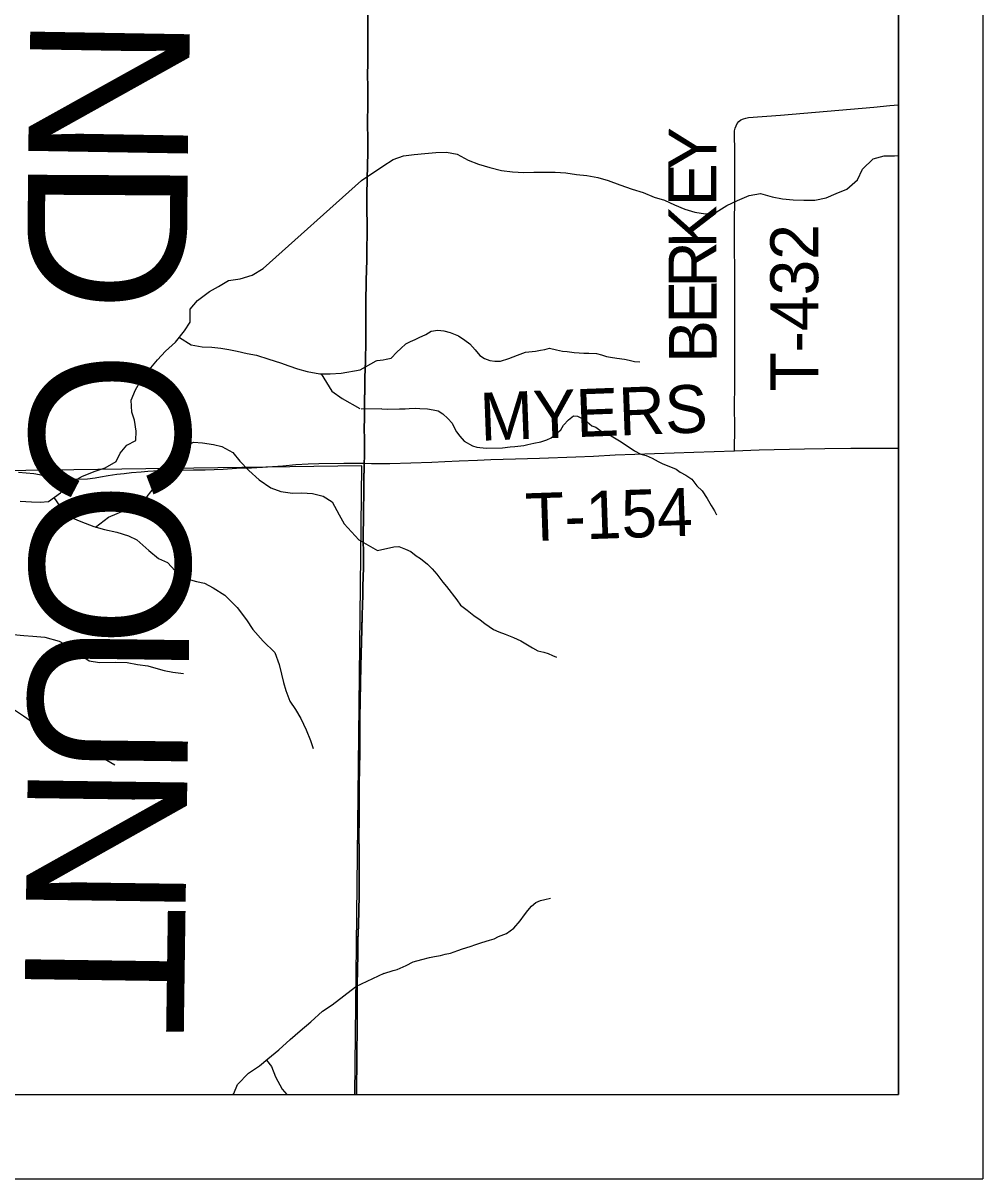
# Model space of a CAD drawing. Extents: x 0 to 34, y 0 to 22.
# Drawn here: x 7.861 to 9, y 14 to 15.371 of the extents above; entities that cross this region are included whole.
import ezdxf

# ---------------------------------------------------------------- set-up
doc = ezdxf.new("R2010")
doc.units = 0
for name, color, linetype in [('Default', 7, 'Continuous'), ('GM_X_County_Text', 7, 'Continuous'), ('GM_X_Interstate_Route', 7, 'Continuous'), ('GM_X_Minor_River', 7, 'Continuous'), ('GM_X_Township_Road', 7, 'Continuous'), ('GM_X_Township_Road_Text', 7, 'Continuous'), ('SH_Cut_Line', 7, 'Continuous'), ('SH_Data', 7, 'Continuous')]:
    doc.layers.add(name, color=color, linetype=linetype)

msp = doc.modelspace()

# ---------------------------------------------------------------- linework, layer by layer
at = {"layer": 'Default'}
msp.add_lwpolyline([(7.1737, 14.1), (8.2548, 14.1), (8.263, 14.8458), (7.1806, 14.8307)], close=True, dxfattribs=at)
at = {"layer": 'GM_X_Interstate_Route'}
for points in [[(8.2703, 15.3819), (8.2702, 15.3628), (8.2701, 15.3535), (8.2702, 15.3459), (8.2703, 15.3357), (8.2701, 15.3227), (8.27, 15.3103), (8.2701, 15.2947), (8.2702, 15.2762), (8.27, 15.2515), (8.2703, 15.2332), (8.2703, 15.2173), (8.2694, 15.1864), (8.2691, 15.1669), (8.2692, 15.1484), (8.2694, 15.1335), (8.2694, 15.1187), (8.2692, 15.106), (8.2691, 15.0903), (8.2683, 15.0658), (8.2681, 15.0391), (8.268, 15.0245), (8.2678, 15.0102), (8.268, 14.9935), (8.2674, 14.9699), (8.2669, 14.9504), (8.2669, 14.9375), (8.2665, 14.9229), (8.2663, 14.9134), (8.2662, 14.904), (8.2661, 14.8885), (8.2662, 14.8792), (8.2662, 14.8689), (8.2663, 14.8563), (8.2661, 14.8495), (8.266, 14.8449), (8.2656, 14.8297), (8.2654, 14.8172), (8.2651, 14.7896), (8.2649, 14.7585), (8.2651, 14.742), (8.2651, 14.7239), (8.2649, 14.715), (8.2645, 14.7023), (8.2642, 14.6921), (8.2638, 14.681), (8.2637, 14.6681), (8.2629, 14.637), (8.2621, 14.609), (8.2609, 14.5469), (8.2607, 14.5068), (8.2606, 14.4854), (8.2602, 14.4707), (8.2602, 14.4471), (8.26, 14.4256), (8.2595, 14.407), (8.26, 14.3884), (8.26, 14.3612), (8.2602, 14.3362), (8.2593, 14.3015), (8.2586, 14.2834), (8.2586, 14.2645), (8.258, 14.25), (8.2577, 14.228), (8.2575, 14.2115), (8.2575, 14.1836), (8.2572, 14.1432), (8.2568, 14.1028), (8.2568, 14.1), (8.9, 14.1), (8.9, 16.8746)], [(3.2011, 14.1), (8.2568, 14.1), (8.2568, 14.1028), (8.2572, 14.1432), (8.2575, 14.1836), (8.2575, 14.2115), (8.2577, 14.228), (8.258, 14.25), (8.2586, 14.2645), (8.2586, 14.2834), (8.2593, 14.3015), (8.2602, 14.3362), (8.26, 14.3612), (8.26, 14.3884), (8.2595, 14.407), (8.26, 14.4256), (8.2602, 14.4471), (8.2602, 14.4707), (8.2606, 14.4854), (8.2607, 14.5068), (8.2609, 14.5469), (8.2621, 14.609), (8.2629, 14.637), (8.2637, 14.6681), (8.2638, 14.681), (8.2642, 14.6921), (8.2645, 14.7023), (8.2649, 14.715), (8.2651, 14.7239), (8.2651, 14.742), (8.2649, 14.7585), (8.2651, 14.7896), (8.2654, 14.8172), (8.2656, 14.8297), (8.266, 14.8449), (8.2661, 14.8495), (8.2663, 14.8563), (8.2662, 14.8689), (8.2662, 14.8792), (8.2661, 14.8885), (8.2662, 14.904), (8.2663, 14.9134), (8.2665, 14.9229), (8.2669, 14.9375), (8.2669, 14.9504), (8.2674, 14.9699), (8.268, 14.9935), (8.2678, 15.0102), (8.268, 15.0245), (8.2681, 15.0391), (8.2683, 15.0658), (8.2691, 15.0903), (8.2692, 15.106), (8.2694, 15.1187), (8.2694, 15.1335), (8.2692, 15.1484), (8.2691, 15.1669), (8.2694, 15.1864), (8.2703, 15.2173), (8.2703, 15.2332), (8.27, 15.2515), (8.2702, 15.2762), (8.2701, 15.2947), (8.27, 15.3103), (8.2701, 15.3227), (8.2703, 15.3357), (8.2702, 15.3459), (8.2701, 15.3535), (8.2702, 15.3628), (8.2703, 15.3819)]]:
    msp.add_lwpolyline(points, dxfattribs=at)
at = {"layer": 'GM_X_Minor_River'}
for points in [[(8.2626, 15.1841), (8.288, 15.2014), (8.3003, 15.2092), (8.3125, 15.2136), (8.3251, 15.2153), (8.338, 15.2163), (8.351, 15.2176), (8.3635, 15.2178), (8.3761, 15.2154), (8.3893, 15.2084), (8.4014, 15.2037), (8.415, 15.1997), (8.429, 15.1961), (8.4419, 15.1944), (8.4552, 15.1938), (8.4674, 15.194), (8.4803, 15.1942), (8.4925, 15.1941), (8.5054, 15.1935), (8.518, 15.1914), (8.5301, 15.1901), (8.543, 15.1877), (8.5555, 15.1841), (8.5691, 15.179), (8.5839, 15.1738), (8.5968, 15.1699), (8.61, 15.1644), (8.6221, 15.1608), (8.6342, 15.1553), (8.6463, 15.1502), (8.6584, 15.1466), (8.671, 15.1449), (8.6835, 15.1466), (8.6962, 15.1548), (8.7088, 15.1607), (8.7226, 15.1663), (8.736, 15.1688), (8.75, 15.1648), (8.7621, 15.1627), (8.775, 15.1614), (8.7876, 15.1608), (8.8005, 15.161), (8.8139, 15.1639), (8.8261, 15.1687), (8.8387, 15.1738), (8.8514, 15.1851), (8.8573, 15.1976), (8.8697, 15.2099), (8.8827, 15.2136), (8.8952, 15.2134), (8.9, 15.2139)], [(8.2626, 15.1841), (8.1463, 15.0797)], [(7.8577, 14.8038), (7.8713, 14.803), (7.8816, 14.8027), (7.8914, 14.8035), (7.9058, 14.8138), (7.9198, 14.8267), (7.9319, 14.8336), (7.9467, 14.8393), (7.9588, 14.8435), (7.9717, 14.8508), (7.9766, 14.8607), (7.9842, 14.8702), (7.9951, 14.8759), (7.9955, 14.8869), (7.9936, 14.8998), (7.9905, 14.9096), (7.9897, 14.9237), (7.9946, 14.9358), (8.0006, 14.9461), (8.0089, 14.9575), (8.0207, 14.9716), (8.0301, 14.9819), (8.0422, 14.9925), (8.0528, 15.0058), (8.0596, 15.0161), (8.0596, 15.0317), (8.0683, 15.0419), (8.0826, 15.0526), (8.0932, 15.0587), (8.105, 15.0656), (8.119, 15.0675), (8.133, 15.0721), (8.1463, 15.0797)], [(8.2812, 14.9707), (8.2886, 14.9714), (8.2922, 14.9723), (8.2979, 14.9736), (8.3047, 14.9805), (8.3096, 14.9851), (8.3153, 14.9904), (8.321, 14.9931), (8.3263, 14.9958), (8.3312, 14.9981), (8.3392, 15.0016), (8.3456, 15.0054), (8.3532, 15.0066), (8.3604, 15.0059), (8.368, 15.004), (8.3779, 14.9999), (8.3855, 14.995), (8.3912, 14.9904), (8.3977, 14.9836), (8.4031, 14.9768), (8.4088, 14.973), (8.4149, 14.9708), (8.4209, 14.97), (8.4278, 14.9701), (8.4376, 14.9731), (8.4429, 14.9751), (8.4478, 14.977), (8.4573, 14.9805), (8.4694, 14.982), (8.4751, 14.9832), (8.4804, 14.984), (8.4857, 14.9852), (8.4941, 14.9833), (8.5013, 14.9818), (8.5066, 14.9814), (8.515, 14.9803), (8.5211, 14.98), (8.5264, 14.9796), (8.5325, 14.9793), (8.5416, 14.9789), (8.5477, 14.9774), (8.5534, 14.9756), (8.5583, 14.9748), (8.5659, 14.9737), (8.575, 14.9723), (8.5803, 14.9711), (8.5868, 14.9696), (8.5929, 14.9693)], [(8.0467, 14.9982), (8.0608, 14.9895), (8.0737, 14.9869), (8.0851, 14.9866), (8.0957, 14.9855), (8.1052, 14.984), (8.1151, 14.9817), (8.1272, 14.9791), (8.1382, 14.9769), (8.1527, 14.9724), (8.1667, 14.9679), (8.1766, 14.9645), (8.1868, 14.9607), (8.1982, 14.9577), (8.2134, 14.9551), (8.2256, 14.9548), (8.2388, 14.9556), (8.2611, 14.9596)], [(8.2611, 14.9596), (8.2802, 14.9705), (8.2812, 14.9707)], [(8.215, 14.9551), (8.2274, 14.9345), (8.24, 14.9258), (8.2608, 14.9138)], [(8.2869, 14.9135), (8.2623, 14.9131)], [(8.2869, 14.9135), (8.2933, 14.9132), (8.3077, 14.9136), (8.3146, 14.9136), (8.3195, 14.914), (8.3267, 14.9141), (8.332, 14.9137), (8.3411, 14.9134), (8.348, 14.9123), (8.3537, 14.9112), (8.3594, 14.9074), (8.3651, 14.9021), (8.3705, 14.8964), (8.3728, 14.8911), (8.3754, 14.8862), (8.3793, 14.8809), (8.3846, 14.8752), (8.3945, 14.8695), (8.3995, 14.868), (8.4105, 14.8669), (8.4302, 14.867), (8.4393, 14.8682), (8.4446, 14.8686), (8.4552, 14.8698), (8.4602, 14.871), (8.4674, 14.8725), (8.4757, 14.8741), (8.4825, 14.8768), (8.4878, 14.8791), (8.4927, 14.8829), (8.4992, 14.8886), (8.5025, 14.894), (8.5082, 14.9005), (8.5143, 14.905), (8.5192, 14.9047), (8.5276, 14.9002), (8.536, 14.8934), (8.5409, 14.8915), (8.547, 14.8869), (8.5519, 14.8854), (8.5588, 14.8813), (8.5687, 14.8753), (8.579, 14.8688), (8.5866, 14.8636), (8.5942, 14.8598), (8.6007, 14.8579), (8.6075, 14.8549), (8.6147, 14.8511), (8.6204, 14.8481), (8.6273, 14.8455), (8.636, 14.8417), (8.641, 14.8383), (8.6475, 14.8349), (8.6547, 14.83), (8.6608, 14.8221), (8.6669, 14.816), (8.673, 14.8069), (8.6776, 14.7986), (8.6815, 14.7925), (8.6838, 14.7876)], [(7.9473, 14.7731), (7.9628, 14.7851), (7.9833, 14.7936), (7.9965, 14.8012), (8.0086, 14.8096), (8.0173, 14.8206), (8.0244, 14.8336), (8.0323, 14.8431), (8.0406, 14.8557), (8.0527, 14.8686), (8.0633, 14.874), (8.0743, 14.8732), (8.0872, 14.871), (8.097, 14.8687), (8.1103, 14.8616), (8.1186, 14.8513), (8.1293, 14.8404), (8.1414, 14.829), (8.1551, 14.8199), (8.1672, 14.8154), (8.1809, 14.8135), (8.1918, 14.8136), (8.2047, 14.8129), (8.2172, 14.8099), (8.2278, 14.803), (8.2362, 14.7875), (8.2423, 14.7769), (8.2596, 14.7581)], [(7.8979, 14.8081), (7.9102, 14.7903), (7.9204, 14.7839), (7.9299, 14.7797), (7.9451, 14.7737), (7.958, 14.7703), (7.9724, 14.7673), (7.9864, 14.7628), (7.9963, 14.7579), (8.0103, 14.7454), (8.0221, 14.7359), (8.0327, 14.731), (8.0418, 14.7212), (8.0543, 14.7121), (8.0672, 14.7087), (8.0767, 14.7065), (8.0869, 14.7012), (8.1006, 14.6925), (8.1154, 14.6777), (8.1264, 14.6633), (8.134, 14.6516), (8.1462, 14.6379), (8.1599, 14.6243), (8.1652, 14.6103), (8.1679, 14.5985), (8.1702, 14.5886), (8.1729, 14.5791), (8.1778, 14.5666), (8.1843, 14.5568), (8.1908, 14.5462), (8.1972, 14.5325), (8.2022, 14.52), (8.2053, 14.5105)], [(8.2596, 14.7581), (8.2819, 14.7453)], [(8.2819, 14.7453), (8.3011, 14.7497), (8.3071, 14.7501), (8.3151, 14.7471), (8.3212, 14.7441), (8.3276, 14.7392), (8.3326, 14.7358), (8.341, 14.729), (8.3467, 14.7237), (8.352, 14.7172), (8.3593, 14.7077), (8.3635, 14.7028), (8.3757, 14.6869), (8.3803, 14.6805), (8.3883, 14.6744), (8.396, 14.6684), (8.4036, 14.6631), (8.4093, 14.6589), (8.4192, 14.6517), (8.4257, 14.6487), (8.4333, 14.6461), (8.4432, 14.6423), (8.4519, 14.6382), (8.4599, 14.6333), (8.4656, 14.6299), (8.4721, 14.6265), (8.4793, 14.6246), (8.4842, 14.6231), (8.4892, 14.6209), (8.4941, 14.619)], [(7.8494, 14.6459), (7.8623, 14.6444), (7.8729, 14.6437), (7.887, 14.6426), (7.904, 14.6377), (7.9143, 14.6324), (7.9268, 14.6234), (7.9398, 14.6143), (7.9519, 14.6124), (7.9713, 14.6129), (7.9849, 14.6125), (7.9971, 14.6103), (8.0092, 14.6084), (8.0187, 14.6058), (8.0286, 14.6032), (8.0388, 14.6009), (8.0517, 14.5995)], [(7.6894, 14.6185), (7.7001, 14.5938), (7.713, 14.584), (7.7267, 14.5806), (7.7388, 14.5807), (7.7513, 14.5841), (7.7612, 14.586), (7.771, 14.5868), (7.7805, 14.5876), (7.793, 14.5854), (7.8056, 14.5805), (7.8155, 14.576), (7.828, 14.5692), (7.8462, 14.5597), (7.8618, 14.5492), (7.8725, 14.5416), (7.8858, 14.5329), (7.8979, 14.5269), (7.9074, 14.5224), (7.9215, 14.5148), (7.931, 14.5107), (7.9405, 14.5073), (7.956, 14.4994), (7.9701, 14.4911)], [(8.2893, 14.2435), (8.3003, 14.247), (8.3052, 14.2485), (8.3158, 14.2532), (8.3241, 14.2574), (8.3343, 14.2601), (8.3434, 14.2624), (8.3495, 14.2636), (8.3567, 14.2651), (8.362, 14.2667), (8.3685, 14.2678), (8.3772, 14.2709), (8.3825, 14.2728), (8.3916, 14.2756), (8.3984, 14.2779), (8.4056, 14.2802), (8.4147, 14.2833), (8.42, 14.2848), (8.4253, 14.2875), (8.4348, 14.291), (8.4435, 14.2975), (8.451, 14.3062), (8.4563, 14.3131), (8.46, 14.3185), (8.4646, 14.3234), (8.4695, 14.328), (8.4752, 14.3303), (8.4801, 14.3315), (8.4869, 14.333)], [(8.2893, 14.2435), (8.2555, 14.2279)], [(8.1105, 14.1), (8.1112, 14.1014), (8.1157, 14.1121), (8.1286, 14.1254), (8.1418, 14.1342), (8.1517, 14.1422), (8.1649, 14.1532), (8.1782, 14.1654), (8.1899, 14.1757), (8.2027, 14.1863), (8.2167, 14.1989), (8.2281, 14.2065), (8.2555, 14.2279)], [(8.1501, 14.1409), (8.1559, 14.1334), (8.1608, 14.1209), (8.1688, 14.1065), (8.1743, 14.1)]]:
    msp.add_lwpolyline(points, dxfattribs=at)
at = {"layer": 'GM_X_Township_Road'}
msp.add_line((8.2663, 14.848), (8.2663, 14.8489), dxfattribs=at)
for points in [[(8.2663, 14.8489), (8.2665, 14.8558), (8.2664, 14.8683), (8.2664, 14.8787), (8.2663, 14.888), (8.2664, 14.9035), (8.2666, 14.9128), (8.2667, 14.9223), (8.2671, 14.937), (8.2671, 14.9499), (8.2676, 14.9694), (8.2682, 14.993), (8.268, 15.0096), (8.2682, 15.0239), (8.2684, 15.0386), (8.2685, 15.0652), (8.2693, 15.0898), (8.2694, 15.1055), (8.2696, 15.1182), (8.2696, 15.1329), (8.2694, 15.1479), (8.2693, 15.1663), (8.2696, 15.1858), (8.2705, 15.2168), (8.2705, 15.2327), (8.2702, 15.2509), (8.2704, 15.2756), (8.2703, 15.2942), (8.2702, 15.3097), (8.2703, 15.3222), (8.2705, 15.3352), (8.2704, 15.3454), (8.2703, 15.353), (8.2704, 15.3623), (8.2706, 15.3813)], [(8.7055, 15.2431), (8.7061, 15.2462), (8.7071, 15.2491), (8.7086, 15.2518), (8.7106, 15.2542), (8.713, 15.2561), (8.7158, 15.2576), (8.7188, 15.2584), (8.7219, 15.2589), (8.7597, 15.2616), (8.8014, 15.2652), (8.8708, 15.2713), (8.8896, 15.2733), (8.9, 15.2742)], [(8.7055, 14.8637), (8.7055, 14.8669), (8.7056, 14.8884), (8.7055, 14.9195), (8.7056, 14.9382), (8.7057, 14.9956), (8.7057, 15.0441), (8.7057, 15.0673), (8.7055, 15.1156), (8.7054, 15.1374), (8.7058, 15.1591), (8.7059, 15.1778), (8.7059, 15.1996), (8.7058, 15.2182), (8.7053, 15.24), (8.7055, 15.2431)], [(8.2663, 14.8489), (8.2747, 14.8487), (8.2778, 14.8486), (8.2965, 14.8487), (8.3213, 14.8493), (8.3462, 14.8502), (8.3617, 14.851), (8.3786, 14.8519), (8.4006, 14.8527), (8.4164, 14.8532), (8.4456, 14.8541), (8.4741, 14.8549), (8.5172, 14.8565), (8.5381, 14.8573), (8.5637, 14.8587), (8.6103, 14.8603), (8.6569, 14.8619), (8.7055, 14.8637)], [(8.7055, 14.8637), (8.7346, 14.8648), (8.7884, 14.8659)], [(8.7884, 14.8659), (8.8123, 14.8664), (8.8434, 14.8669), (8.8839, 14.8668), (8.9, 14.8668)], [(7.8558, 14.8382), (7.8651, 14.8374), (7.8742, 14.8366), (7.8806, 14.8355), (7.8886, 14.8337), (7.8987, 14.8317), (7.906, 14.8307), (7.9142, 14.83), (7.925, 14.8298), (7.9377, 14.8304), (7.9467, 14.8315), (7.9531, 14.8326), (7.9624, 14.8343), (7.9724, 14.8358), (7.9814, 14.8369), (7.9901, 14.8378), (8.0014, 14.8388), (8.0091, 14.8393), (8.0161, 14.8397), (8.0233, 14.8402), (8.0347, 14.8407), (8.0635, 14.8409), (8.0775, 14.8411), (8.0986, 14.842), (8.1144, 14.8429), (8.1322, 14.8436), (8.1454, 14.8442), (8.1571, 14.8452), (8.1696, 14.846), (8.1848, 14.8473), (8.1997, 14.8481), (8.2122, 14.8485), (8.242, 14.849), (8.2596, 14.849), (8.2663, 14.8489)], [(8.257, 14.1), (8.257, 14.1022), (8.2574, 14.1426), (8.2577, 14.1831), (8.2577, 14.211), (8.2579, 14.2274), (8.2582, 14.2494), (8.2588, 14.2639), (8.2588, 14.2829), (8.2595, 14.3009), (8.2604, 14.3356), (8.2602, 14.3607), (8.2602, 14.3879), (8.2597, 14.4065), (8.2602, 14.4251), (8.2604, 14.4465), (8.2604, 14.4701), (8.2608, 14.4848), (8.2609, 14.5063), (8.2611, 14.5463), (8.2623, 14.6085), (8.2631, 14.6365), (8.2639, 14.6675), (8.264, 14.6805), (8.2644, 14.6916), (8.2647, 14.7018), (8.2651, 14.7145), (8.2653, 14.7233), (8.2653, 14.7415), (8.2651, 14.7579), (8.2653, 14.7891), (8.2656, 14.8166), (8.2658, 14.8291), (8.2662, 14.8443), (8.2663, 14.848)]]:
    msp.add_lwpolyline(points, dxfattribs=at)
at = {"layer": 'SH_Cut_Line'}
for points in [[(8.2703, 15.3819), (8.2702, 15.3628), (8.2701, 15.3535), (8.2702, 15.3459), (8.2703, 15.3357), (8.2701, 15.3227), (8.27, 15.3103), (8.2701, 15.2947), (8.2702, 15.2762), (8.27, 15.2515), (8.2703, 15.2332), (8.2703, 15.2173), (8.2694, 15.1864), (8.2691, 15.1669), (8.2692, 15.1484), (8.2694, 15.1335), (8.2694, 15.1187), (8.2692, 15.106), (8.2691, 15.0903), (8.2683, 15.0658), (8.2681, 15.0391), (8.268, 15.0245), (8.2678, 15.0102), (8.268, 14.9935), (8.2674, 14.9699), (8.2669, 14.9504), (8.2669, 14.9375), (8.2665, 14.9229), (8.2663, 14.9134), (8.2662, 14.904), (8.2661, 14.8885), (8.2662, 14.8792), (8.2662, 14.8689), (8.2663, 14.8563), (8.2661, 14.8495), (8.266, 14.8449), (8.2656, 14.8297), (8.2654, 14.8172), (8.2651, 14.7896), (8.2649, 14.7585), (8.2651, 14.742), (8.2651, 14.7239), (8.2649, 14.715), (8.2645, 14.7023), (8.2642, 14.6921), (8.2638, 14.681), (8.2637, 14.6681), (8.2629, 14.637), (8.2621, 14.609), (8.2609, 14.5469), (8.2607, 14.5068), (8.2606, 14.4854), (8.2602, 14.4707), (8.2602, 14.4471), (8.26, 14.4256), (8.2595, 14.407), (8.26, 14.3884), (8.26, 14.3612), (8.2602, 14.3362), (8.2593, 14.3015), (8.2586, 14.2834), (8.2586, 14.2645), (8.258, 14.25), (8.2577, 14.228), (8.2575, 14.2115), (8.2575, 14.1836), (8.2572, 14.1432), (8.2568, 14.1028), (8.2568, 14.1), (8.9, 14.1), (8.9, 20.9)], [(2.1, 14.1), (8.2568, 14.1), (8.2568, 14.1028), (8.2572, 14.1432), (8.2575, 14.1836), (8.2575, 14.2115), (8.2577, 14.228), (8.258, 14.25), (8.2586, 14.2645), (8.2586, 14.2834), (8.2593, 14.3015), (8.2602, 14.3362), (8.26, 14.3612), (8.26, 14.3884), (8.2595, 14.407), (8.26, 14.4256), (8.2602, 14.4471), (8.2602, 14.4707), (8.2606, 14.4854), (8.2607, 14.5068), (8.2609, 14.5469), (8.2621, 14.609), (8.2629, 14.637), (8.2637, 14.6681), (8.2638, 14.681), (8.2642, 14.6921), (8.2645, 14.7023), (8.2649, 14.715), (8.2651, 14.7239), (8.2651, 14.742), (8.2649, 14.7585), (8.2651, 14.7896), (8.2654, 14.8172), (8.2656, 14.8297), (8.266, 14.8449), (8.2661, 14.8495), (8.2663, 14.8563), (8.2662, 14.8689), (8.2662, 14.8792), (8.2661, 14.8885), (8.2662, 14.904), (8.2663, 14.9134), (8.2665, 14.9229), (8.2669, 14.9375), (8.2669, 14.9504), (8.2674, 14.9699), (8.268, 14.9935), (8.2678, 15.0102), (8.268, 15.0245), (8.2681, 15.0391), (8.2683, 15.0658), (8.2691, 15.0903), (8.2692, 15.106), (8.2694, 15.1187), (8.2694, 15.1335), (8.2692, 15.1484), (8.2691, 15.1669), (8.2694, 15.1864), (8.2703, 15.2173), (8.2703, 15.2332), (8.27, 15.2515), (8.2702, 15.2762), (8.2701, 15.2947), (8.27, 15.3103), (8.2701, 15.3227), (8.2703, 15.3357), (8.2702, 15.3459), (8.2701, 15.3535), (8.2702, 15.3628), (8.2703, 15.3819)]]:
    msp.add_lwpolyline(points, dxfattribs=at)
at = {"layer": 'SH_Data'}
for p, q in [((9, 21), (9, 14)), ((8.9, 20.9), (8.9, 14.1)), ((2.1, 14.1), (8.9, 14.1)), ((2, 14), (9, 14))]:
    msp.add_line(p, q, dxfattribs=at)

# ---------------------------------------------------------------- texts
at = {"layer": 'GM_X_County_Text'}
for s, rotation, p in [('N', 269.0384, (7.8701, 15.3817)), ('D', 269.6887, (7.8672, 15.2119)), ('C', 270.9523, (7.8678, 14.9811)), ('O', 269.5607, (7.8704, 14.8281)), ('U', 269.2975, (7.8691, 14.6609)), ('N', 269.2094, (7.867, 14.4935)), ('T', 269.1926, (7.8647, 14.326))]:
    msp.add_text(s, height=0.1894, rotation=rotation, dxfattribs=at).set_placement(p)
at = {"layer": 'GM_X_Township_Road_Text'}
for s, height, rotation, p in [('Y', 0.0568, 89.2769, (8.6836, 15.1962)), ('E', 0.0568, 90.1693, (8.6837, 15.1539)), ('K', 0.0568, 90.1723, (8.6839, 15.1039)), ('T-432', 0.05682, 90, (8.8046, 14.934)), ('R', 0.0568, 90.1738, (8.684, 15.0573)), ('E', 0.0568, 90.1714, (8.6842, 15.0147)), ('B', 0.0568, 90.1737, (8.6843, 14.9681)), ('MYERS', 0.05682, 2.1721, (8.4043, 14.8755)), ('T-154', 0.05682, 1.9465, (8.458, 14.7563))]:
    msp.add_text(s, height=height, rotation=rotation, dxfattribs=at).set_placement(p)

doc.saveas('drawing.dxf')
